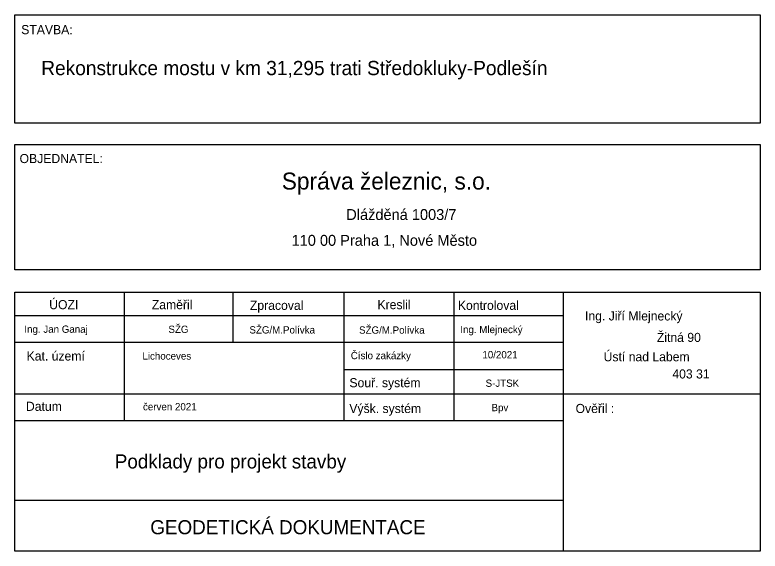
# Model space of a CAD drawing. Extents: x -879530 to -879371, y -1019242 to -1019127.
import ezdxf

# ---------------------------------------------------------------- set-up
doc = ezdxf.new("R2010")
doc.units = 0
doc.layers.add('tabulka', color=7, linetype='Continuous')

msp = doc.modelspace()

# ---------------------------------------------------------------- linework, layer by layer
at = {"layer": 'tabulka'}
for p, q in [((-879530.09, -1019186.45), (-879371.44, -1019186.45)), ((-879506.8, -1019186.45), (-879506.8, -1019213.77)), ((-879483.66, -1019186.45), (-879483.66, -1019197.07)), ((-879460.06, -1019186.45), (-879460.06, -1019213.77)), ((-879436.61, -1019186.45), (-879436.61, -1019213.77)), ((-879413.31, -1019241.58), (-879413.31, -1019186.45)), ((-879530.09, -1019191.36), (-879413.31, -1019191.36)), ((-879530.09, -1019197.07), (-879413.31, -1019197.07)), ((-879460.06, -1019202.88), (-879413.31, -1019202.88)), ((-879530.09, -1019208.07), (-879371.44, -1019208.07)), ((-879530.09, -1019213.77), (-879413.31, -1019213.77)), ((-879530.09, -1019230.76), (-879413.31, -1019230.76))]:
    msp.add_line(p, q, dxfattribs=at)
for points in [[(-879530.09, -1019127.36), (-879371.44, -1019127.36), (-879371.44, -1019150.43), (-879530.09, -1019150.43)], [(-879530.09, -1019154.95), (-879371.44, -1019154.95), (-879371.44, -1019181.64), (-879530.09, -1019181.64)]]:
    msp.add_lwpolyline(points, close=True, dxfattribs=at)
msp.add_lwpolyline([(-879371.44, -1019186.45), (-879371.44, -1019241.58), (-879530.09, -1019241.58), (-879530.09, -1019186.45)], dxfattribs=at)

# ---------------------------------------------------------------- texts
for s, height, p in [('STAVBA:', 1.94, (-879528.75, -1019131.47)), ('Rekonstrukce mostu v km 31,295 trati Středokluky-Podlešín', 3.04, (-879524.48, -1019140.2)), ('OBJEDNATEL:', 1.94, (-879529.1, -1019158.93)), ('Správa železnic, s.o.', 3.61, (-879473.27, -1019164.56)), ('Dlážděná 1003/7', 2.32, (-879459.55, -1019171.05)), ('110 00 Praha 1, Nové Město', 2.32, (-879471.19, -1019176.55)), ('ÚOZI', 1.94, (-879522.79, -1019190.05)), ('Zaměřil', 1.94, (-879500.95, -1019190.05)), ('Zpracoval', 1.94, (-879480.06, -1019190.2)), ('Kreslil', 1.94, (-879452.9, -1019190.05)), ('Kontroloval', 1.94, (-879435.78, -1019190.2)), ('Ing. Jiří Mlejnecký', 1.94, (-879408.71, -1019192.45)), ('Ing. Jan Ganaj', 1.552, (-879528.08, -1019195.08)), ('SŽG', 1.552, (-879497.41, -1019195.11)), ('SŽG/M.Polívka', 1.552, (-879480.16, -1019195.23)), ('SŽG/M.Polívka', 1.552, (-879456.82, -1019195.27)), ('Ing. Mlejnecký', 1.552, (-879435.26, -1019195.15)), ('Žitná 90', 1.94, (-879393.42, -1019197.03)), ('Kat. území', 1.94, (-879527.6, -1019200.99)), ('Lichoceves', 1.552, (-879502.94, -1019200.79)), ('Číslo zakázky', 1.552, (-879458.58, -1019200.7)), ('10/2021', 1.552, (-879430.56, -1019200.52)), ('Ústí nad Labem', 1.94, (-879404.75, -1019201.15)), ('403 31', 1.94, (-879390.12, -1019204.81)), ('Souř. systém', 1.94, (-879458.87, -1019206.68)), ('S-JTSK', 1.552, (-879429.88, -1019206.59)), ('Datum', 1.94, (-879527.74, -1019211.71)), ('červen 2021', 1.552, (-879502.82, -1019211.6)), ('Výšk. systém', 1.94, (-879458.89, -1019212.17)), ('Bpv', 1.552, (-879428.62, -1019211.78)), ('Ověřil :', 1.94, (-879410.72, -1019212.17)), ('Podklady pro projekt stavby', 3, (-879508.83, -1019223.98)), ('GEODETICKÁ DOKUMENTACE ', 3, (-879501.27, -1019237.99))]:
    msp.add_text(s, height=height, dxfattribs=at).set_placement(p)

doc.saveas('drawing.dxf')
